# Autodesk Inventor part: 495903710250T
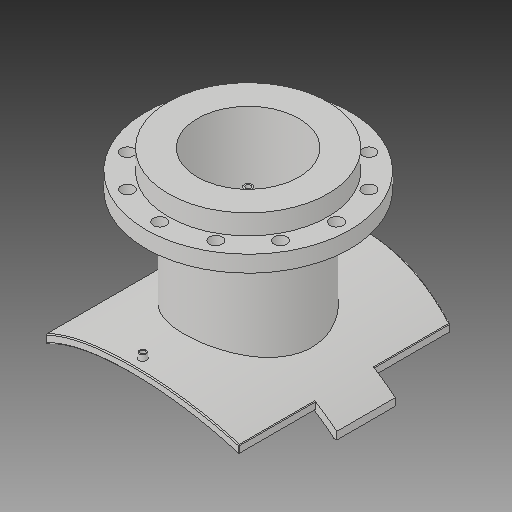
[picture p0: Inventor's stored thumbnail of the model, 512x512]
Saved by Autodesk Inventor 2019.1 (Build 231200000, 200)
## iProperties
Created: 2017-10
Part Number: 495903710250T
Material: Generic
Description: PLASSON FLANGED BRANCH SADDLE 710X250
Document SubType Name: Modeling
Designer: KIM
Mass: 2339.99 g
Surface Area: 3251.55 cm^2
Volume: 2339.99 cm^3
Density: 1 g/cm^3
Appearance: Default
Author: KIM
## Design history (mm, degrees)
derived "495904_495903.ipt"
feature "Solid1::495904_495903.ipt"
feature "Solid2::495904_495903.ipt"
tag "TaggingFeature1"
body "Solid1"
other parameters: "d1" = 15, "d2" = 387, "d4" = 0, "d6" = 117.5, "d7" = 0, "d12" = 380.6, "d13" = 14, "d14" = 211.5, "d16" = 5 deg, "d18" = 4, "d19" = 14, "d20" = 0, "d21" = 3, "d22" = 0, "d23" = 645, "d36" = 211.5, "d38" = 0, "d39" = 2, "d41" = 204, "d46" = 256, "d47" = 16, "d48" = 10.4, "d49" = 192.5, "d51" = 724.2, "d53" = 0, "d54" = 26, "d55" = 177.5, "d57" = 0, "d59" = 360 deg, "d61" = 33, "d63" = 0, "d66" = 275, "d67" = 15, "d68" = 137.5, "d70" = 0, "d71" = 2, "H_" = 275, "x_" = 15, "D_" = 16, "DN_" = 204, "t_" = 33, "s_" = 26, "Dp_" = 355
